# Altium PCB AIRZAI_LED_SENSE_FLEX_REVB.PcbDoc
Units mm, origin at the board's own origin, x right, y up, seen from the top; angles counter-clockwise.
Board outline 68.92 x 111.6 mm, 2 copper layers (Top Layer, Bottom Layer); 53 components, 36 nets, 162 pads, 42 vias.
Unrouted connection lines stored in the file: 83.
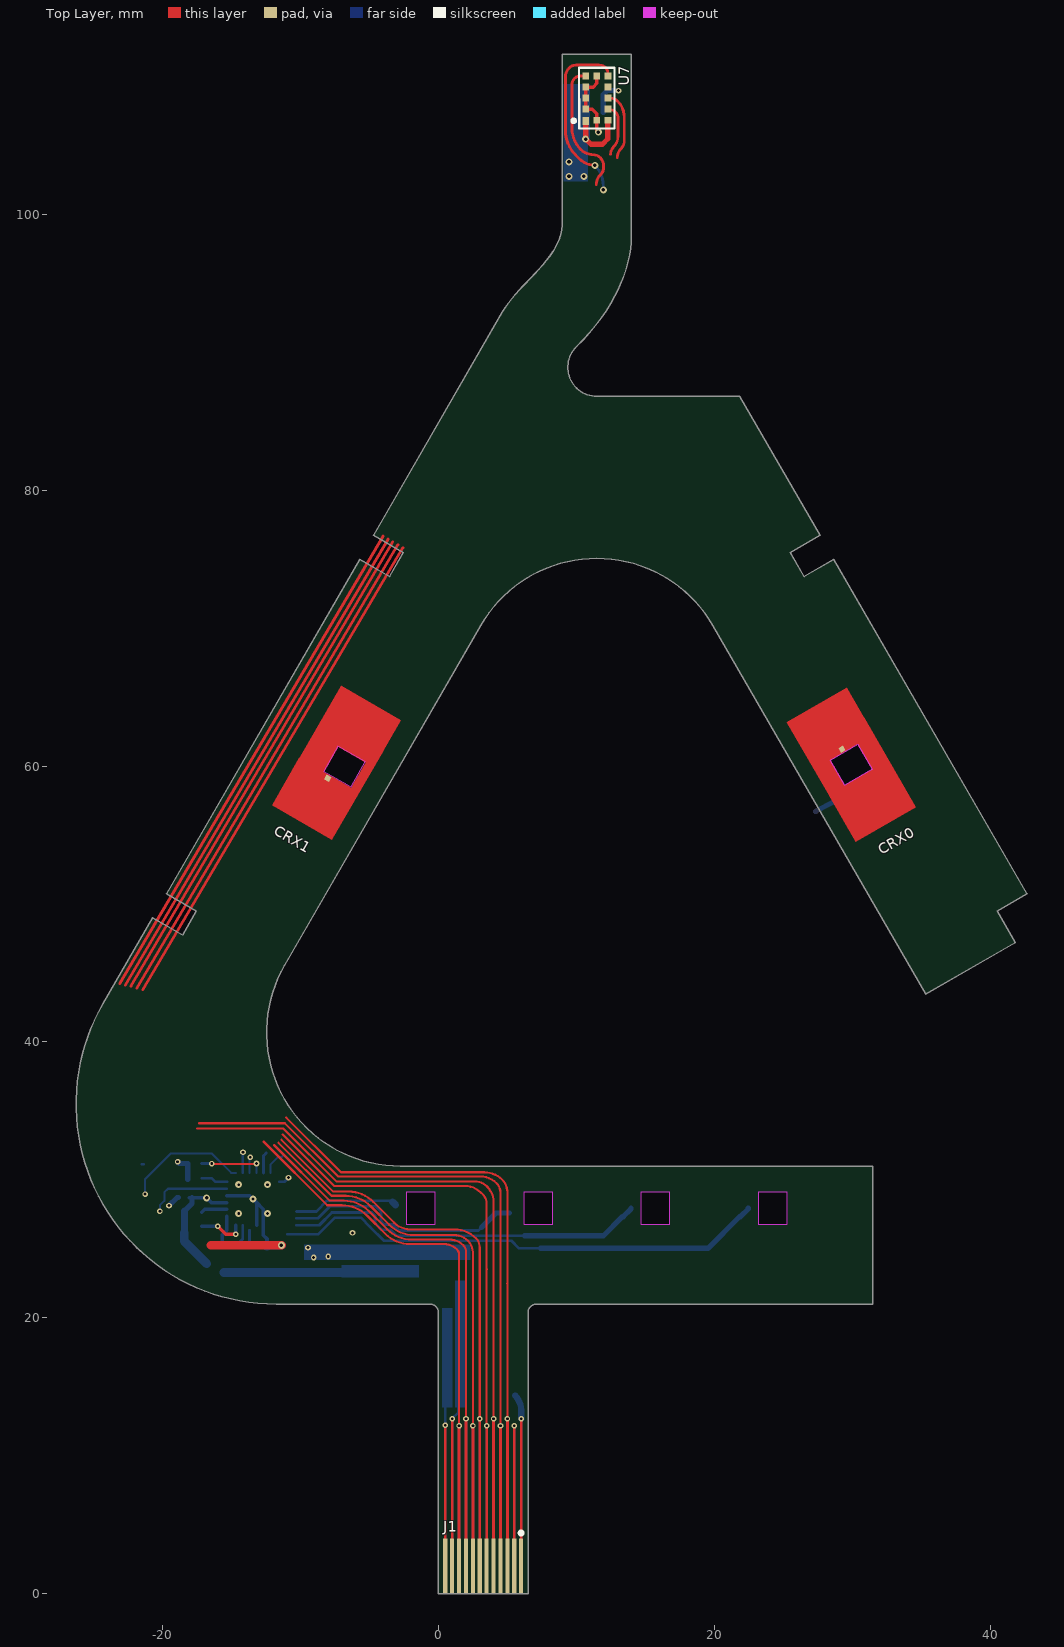
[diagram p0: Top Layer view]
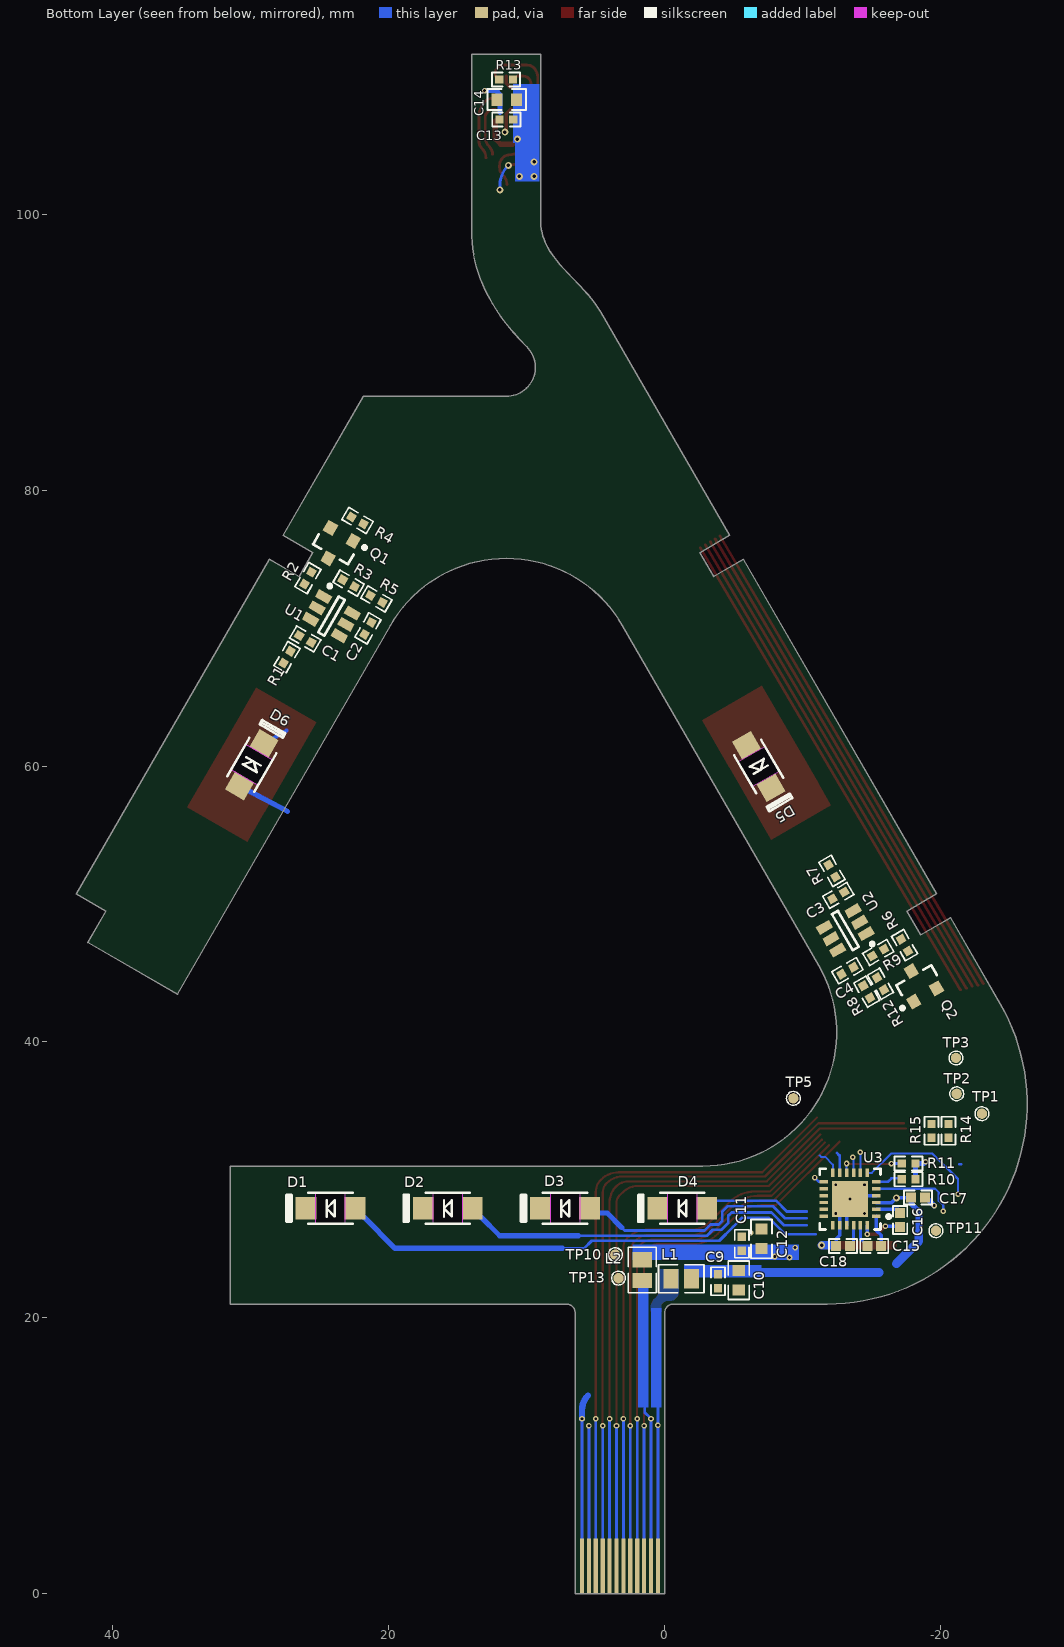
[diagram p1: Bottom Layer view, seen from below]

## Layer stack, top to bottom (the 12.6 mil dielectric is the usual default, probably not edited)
Top Solder: solder mask 0.0102, Solder Resist, Dk 3.5
Top Layer: signal copper 0.0356
Dielectric 1: dielectric 0.32, FR-4, Dk 4.8
Bottom Layer: signal copper 0.0356
Bottom Solder: solder mask 0.0102, Solder Resist, Dk 3.5

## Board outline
-11.76,21 cw(c-11.76,35.5) -24.317,42.751 -20.705,49.007 -18.54,47.757 -17.54,49.489 -19.705,50.739 -5.704,74.987 -3.539,73.736 -2.539,75.468 -4.704,76.719 4.638,92.9 cw(c11.813,88.612) 5.59,94.192 cw(c21.327,80.391) 6.151,94.807 6.73,95.412 ccw(c-15.943,117.23) 7.299,96.019 ccw(c-2.377,104.855) 7.828,96.636 ccw(c1.874,101.436) 8.29,97.273 ccw(c4.018,100.047) 8.655,97.94 ccw(c5.183,99.515) 8.895,98.645 ccw(c5.64,99.401) 8.982,99.4 8.982,100.4 8.982,111.6 13.982,111.6 13.982,100.4 13.982,98.4 cw(c6.078,98.429) 13.773,96.625 cw(c4.661,98.734) 13.526,95.753 cw(c3.528,99.114) 13.197,94.898 cw(c2.331,99.634) 12.794,94.065 cw(c0.618,100.569) 11.807,92.484 cw(c-1.263,101.927) 10.012,90.4 ccw(c11.481,88.9) 11.481,86.8 21.846,86.799 27.666,76.718 25.501,75.468 26.501,73.736 28.666,74.986 42.665,50.737 40.5,49.487 41.816,47.209 35.316,43.467 19.881,70.202 ccw(c11.481,65.352) 3.08,70.202 -11.153,45.55 ccw(c-2.753,40.7) -2.753,31 31.48,30.999 31.48,21 7.103,21 ccw(c7.106,20.394) 6.5,20.39 6.5,0 0,0 0,20.381 ccw(c-0.606,20.394) -0.594,21
cut-out: 23.18,26.8 25.28,26.8 25.28,29.1 23.18,29.1
cut-out: 14.68,26.8 16.78,26.8 16.78,29.1 14.68,29.1
cut-out: 6.18,26.8 8.28,26.8 8.28,29.1 6.18,29.1
cut-out: -2.32,26.8 -0.22,26.8 -0.22,29.1 -2.32,29.1
cut-out: 29.454,58.612 28.41,60.425 30.403,61.572 31.447,59.759
cut-out: -8.322,59.637 -6.329,58.49 -5.285,60.303 -7.278,61.45

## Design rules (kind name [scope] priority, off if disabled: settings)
Clearance Clearance_Board_Cutout_Electrodes [(InComponent('CRX0') OR InComponent('CRX1')) vs OnLayer('Multi-Layer')] p1: gap=0 ignorepadtopadclearanceinfootprint=FALSE
Clearance Clearance_Board_Cutout_Diodes [(InComponent('D1') OR InComponent('D2') OR InComponent('D3') OR InComponent('D4') OR InComponent('D5') OR InComponent('D6')) vs OnLayer('Multi-Layer')] p2: gap=0 ignorepadtopadclearanceinfootprint=FALSE
Clearance Clearance_Keepout [(OnLayer('Keep-Out Layer')) vs (InComponent('D1') OR InComponent('D2') OR InComponent('D3') OR InComponent('D4') OR InComponent('D5') OR InComponent('D6') OR InComponent('CRX0') OR InComponent('CRX1') OR InComponent('J1'))] p3: gap=0 ignorepadtopadclearanceinfootprint=FALSE
Clearance Clearance_GND_POLY_ELECTRODE [(InComponent('CRX0') OR InComponent('CRX1') OR InComponent('CRX2') OR InNet('NetCRX0_1') OR InNet('NetCRX1_1') OR InNet('NetCRX2_1') OR InNet('NetR4_2') OR InNet('NetR2_1') OR InNet('NetR1_1')) vs (InNet('GND') AND InPolygon)] p4: gap=0.762 ignorepadtopadclearanceinfootprint=FALSE
Clearance Clearance_POLYGON_KEEPOUT [(OnLayer('Keep-Out Layer')) vs (InNet('GND') AND InPolygon)] p5: gap=0.254 ignorepadtopadclearanceinfootprint=FALSE
Clearance Clearance_GND_POLY_REST [All vs (InNet('GND') AND InPolygon)] p6: gap=0.254 ignorepadtopadclearanceinfootprint=FALSE
Clearance [All] p7: gap=0.152 ignorepadtopadclearanceinfootprint=FALSE
MinimumSolderMaskSliver [All] p1: minsoldermaskwidth=0.025
PolygonConnect [All] p1: connectstyle=Direct reliefconductorwidth=0.254 reliefentries=4 polygonreliefangle="90 Angle" airgapwidth=0.254
RoomDefinition AIRZAI_LED_SENSE_FLEX_REVB [InComponentClass('AIRZAI_LED_SENSE_FLEX_REVB')] p1: confinementstyle=ConfineIn formatcopy=TRUE lockcomponents=FALSE outline -98.86,-68.935 273.504,-68.935 273.504,174.905 -98.86,174.905
RoutingVias [All] p1: holewidth=0.711 width=1.27 viastyle="Through Hole" minholewidth=0.203 minwidth=0.406 maxholewidth=0.711 maxwidth=1.27
SilkToSilkClearance [All] p1: silktosilkclearance=0.025
SilkToSolderMaskClearance [IsPad] p1: minsilkscreentomaskgap=0.051 clearancetoexposedcopper=TRUE
SolderMaskExpansion [All] p1: expansion=0.102
UnRoutedNet [All] p1: checkbadconnections=TRUE
Width [All] p1: maxlimit=2.54 minlimit=0.152 preferedwidth=0.254
26 further rules are at their usual default settings.

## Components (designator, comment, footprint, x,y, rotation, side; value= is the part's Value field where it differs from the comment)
C1 "22nF" 0402CAP 26.059,69.212 r210 bottom
C2 "0.1µF" 0402CAP 21.514,69.977 r120 bottom
C3 "22nF" 0402CAP -12.577,50.624 r330 bottom
C4 "0.1µF" 0402CAP -13.237,45.163 r150 bottom
C9 "0.1µF" 0402CAP -3.861,22.661 r270 bottom
C10 "10µF" 0603 -5.359,22.733 r270 bottom
C11 "0.1µF" 0402CAP -5.588,25.38 r90 bottom
C12 "10µF" 0603 -7.01,25.73 r90 bottom
C13 "0.1µF" 0402CAP 11.481,106.864 r0 bottom
C14 "4.7µF" 0603 11.455,108.306 r180 bottom
C15 "CAP 1uF 16V 0402(1005)" CAPC0402(1005)60_M -15.181,25.222 r0 bottom value=1uF
C16 "CAP 1uF 16V 0402(1005)" CAPC0402(1005)60_M -17.057,27.103 r270 bottom value=1uF
C17 "CAP 1uF 16V 0402(1005)" CAPC0402(1005)60_M -18.357,28.733 r0 bottom value=1uF
C18 "CAP 1uF 16V 0402(1005)" CAPC0402(1005)60_M -12.921,25.222 r0 bottom value=1uF
CRX0 "CONTACT POINT 1" "CONTACT_POINT_1CM _SQ - duplicate" 29.928,60.092 r300 top
CRX1 "CONTACT POINT 1" "CONTACT_POINT_1CM _SQ" -7.375,60.254 r60 top
D1 "WHITE" LED1206_LTW-C230DS 24.23,27.95 r0 bottom locked
D2 "WHITE" LED1206_LTW-C230DS 15.73,27.95 r0 bottom locked
D3 "WHITE" LED1206_LTW-C230DS 7.23,27.95 r0 bottom locked
D4 "WHITE" LED1206_LTW-C230DS -1.271,27.951 r0 bottom
D5 "WHITE" LED1206_LTW-C230DS -6.804,59.97 r240 bottom
D6 "WHITE" LED1206_LTW-C230DS 29.928,60.092 r120 bottom
J1 "FFC Pads" FFC_PADS 3.25,2 r0 top locked
L1 "CB2012T100KR" 0805 -1.194,22.835 r180 bottom value=10uH
L2 "CB2012T100KR" 0805 1.626,23.47 r90 bottom value=10uH
Q1 "NTR4003NT1G" SOT-23-3-NTR4003NT1G 23.904,75.921 r300 bottom
Q2 "NTR4003NT1G" SOT-23-3-NTR4003NT1G -18.368,44.274 r60 bottom
R1 "10k 0402(1005)" 0402 27.38,67.892 r300 bottom value=10k
R2 "100R 0402(1005)" 0402 25.861,73.619 r300 bottom value=100
R3 "Jumper 0402(1005)" 0402 22.911,73.254 r30 bottom value=0R
R4 "DNP 0402(1005)" 0402 22.276,77.8 r30 bottom value=DNP
R5 "DNP 0402(1005)" 0402 20.904,72.111 r210 bottom value=DNP
R6 "100R 0402(1005)" 0402 -17.378,47.017 r60 bottom value=100
R7 "10k 0402(1005)" 0402 -12.119,52.402 r60 bottom value=10k
R8 "Jumper 0402(1005)" 0402 -14.637,43.641 r240 bottom value=0R
R9 "DNP 0402(1005)" 0402 -15.469,46.484 r330 bottom value=DNP
R10 "Jumper 0402(1005)" 0402 -17.668,30.048 r0 bottom value=0R
R11 "Jumper 0402(1005)" 0402 -17.668,31.191 r0 bottom value=0R
R12 "DNP 0402(1005)" 0402 -15.628,44.22 r240 bottom value=DNP
R13 "10k 0402(1005)" 0402 11.506,109.753 r0 bottom value=10k
R14 "Jumper 0402(1005)" 0402 -20.569,33.563 r270 bottom value=0R
R15 "DNP 0402(1005)" 0402 -19.327,33.563 r90 bottom value=DNP
TP1 "Test Point" TP_0.9MM -22.988,34.806 r90 bottom
TP2 "Test Point" TP_0.9MM -21.16,36.248 r90 bottom
TP3 "Test Point" TP_0.9MM -21.105,38.846 r90 bottom
TP5 "Test Point" TP_0.9MM -9.322,35.916 r90 bottom
TP10 "Test Point" TP_0.9MM 3.581,24.587 r90 bottom
TP11 "Test Point" TP_0.9MM -19.657,26.324 r90 bottom
TP13 "Test Point" TP_0.9MM 3.353,22.885 r90 bottom
U1 "AT42QT1010-TSHR" SOT-23-6-AT42QT1010-TSHR 24.154,70.863 r210 bottom
U2 "AT42QT1010-TSHR" SOT-23-6-AT42QT1010-TSHR -13.085,48.084 r330 bottom
U3 "LP55231SQE/NOPB" WQFN-24-LP55231SQE/NOPB -13.43,28.616 r0 bottom value="IC LED DRIVER RGLTR DIM 24WQFN"
U7 "VL53L0CXV0DH/1" VL53L0X 11.481,108.407 r270 top

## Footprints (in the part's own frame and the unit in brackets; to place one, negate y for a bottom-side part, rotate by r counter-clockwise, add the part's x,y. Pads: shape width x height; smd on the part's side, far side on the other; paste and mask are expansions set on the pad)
0402 [mm] "Chip Resistor, Body 1.1x0.5mm, IPC High Density"
  rect 0.6x0.6 smd: 1(-0.5,0) 2(0.5,0)
  silkscreen extent -1.02,-0.51 1.02,0.51, body extent -0.5,-0.25 0.5,0.25, height 0.27
0402CAP [mm] "Chip Capacitor, Body 1.1x0.5mm, IPC High Density"
  rect 0.6x0.6 smd: 1(-0.5,0) 2(0.5,0)
  silkscreen extent -1.02,-0.51 1.02,0.51, body extent -0.5,-0.3 0.5,0.3, height 0.19
0603 [mm] "Chip Resistor, Body 1.6x0.8mm, IPC High Density"
  rect 0.8x0.9 smd: 1(-0.7,0) 2(0.7,0)
  silkscreen extent -1.4,-0.76 1.4,0.76, body extent -0.8,-0.41 0.8,0.4, height 0.37
0805 [mm] "Chip Resistor, Body 2.0x1.3mm, IPC High Density"
  rect 1.1x1.4 smd: 1(-0.75,0) 2(0.75,0)
  silkscreen extent -1.65,-1.02 1.65,1.02, body extent -1.02,-0.64 0.98,0.62, height 0.47
CAPC0402(1005)60_M [mm] "Chip Capacitor, Body 1.0x0.5mm, Height 0.6mm, IPC Low Density"
  rect 0.72x0.72 smd: 1(-0.5,0) 2(0.5,0)
  silkscreen extent -1.02,-0.51 1.02,0.51, body extent -0.55,-0.3 0.55,0.3, height 0.6
"CONTACT_POINT_1CM _SQ" [mm]
  rect 0.4x0.4 smd paste-2 mask-2: 1(-1.312,-0.018)
  Top Layer region: -3.216,2.5 -1.068,0.472 1.05,0.472 1.05,-2.5 5,-2.5 5,2.5
  Top Layer region: 2.48,-2.5 1.768,-1.828 -1.05,-1.828 -1.05,2.5 -5,2.5 -5,-2.5
"CONTACT_POINT_1CM _SQ - duplicate" [mm]
  rect 0.4x0.4 smd paste-2 mask-2: 1(-1.312,-0.018)
  Top Layer region: 2.48,-2.5 1.05,-1.15 -1.05,-1.15 -1.05,2.5 -5,2.5 -5,-2.5
  Top Layer region: -2.48,2.5 -1.05,1.15 1.05,1.15 1.05,-2.5 5,-2.5 5,2.5
FFC_PADS [mm] "(0.50mm"
  rect 0.3x4 smd: 1(2.75,0) 2(2.25,0) 3(1.75,0) 4(1.25,0) 5(0.75,0) 6(0.25,0) 7(-0.25,0) 8(-0.75,0) 9(-1.25,0) 10(-1.75,0) 11(-2.25,0) 12(-2.75,0)
  rect 0.3x4 smd far side: 1(2.75,0) 2(2.25,0) 3(1.75,0) 4(1.25,0) 5(0.75,0) 6(0.25,0) 7(-0.25,0) 8(-0.75,0) 9(-1.25,0) 10(-1.75,0) 11(-2.25,0) 12(-2.75,0)
  silkscreen extent 2.63,2.29 2.87,2.54
LED1206_LTW-C230DS [mm] "Chip Capacitor, Body 3.2x1.6mm, IPC High Density"
  rect 1.5x1.6 smd paste-0.1 mask+0.07: 1(1.775,0) 2(-1.775,0)
  silkscreen extent -1.6,-1.13 3.19,1.13, body extent -1.63,-0.8 1.63,0.8, height 0.31
SOT-23-3-NTR4003NT1G [mm] "SOT23, 3-Leads, Body 2.92x1.3mm, Pitch 0.95mm"
  rect 0.9x0.8 smd: 1(-1,0.95) 2(-1,-0.95) 3(1,0)
  silkscreen extent -1.12,-1.46 0.65,2.02, body extent -0.65,-1.46 0.65,1.46, height 1.11
SOT-23-6-AT42QT1010-TSHR [mm] "SOT23, 6-Leads, Body 2.9x1.6mm, Pitch 0.95mm, Lead Span 2.8mm, IPC Medium Density"
  rect 1.1x0.65 smd: 1(-1.2,0.95) 2(-1.2,0) 3(-1.2,-0.95) 4(1.2,-0.95) 5(1.2,0) 6(1.2,0.95)
  silkscreen extent -1.32,-1.5 0.25,1.95, body extent -0.88,-1.5 0.88,1.5, height 1.45
TP_0.9MM [mm] "0.9MM DIA TESTPOINT"
  round 0.75 smd paste-5 mask+0.05: 1(0,0)
  silkscreen extent -0.5,-0.5 0.5,0.5
VL53L0X [mm]
  rect 0.58x0.5 smd: 1(1.64,-0.8)
  rect 0.5x0.5 smd: 2(0.8,-0.8) 3(0,-0.8) 4(-0.8,-0.8) 5(-1.6,-0.8) 6(-1.6,0) 7(-1.6,0.8) 8(-0.8,0.8) 9(0,0.8) 10(0.8,0.8) 11(1.6,0.8) 12(1.6,0)
  silkscreen extent -2.2,-1.79 2.2,1.3, body extent -2.2,-1.3 2.2,1.3, height 3.72
WQFN-24-LP55231SQE/NOPB [mm] "QFN, 24-Leads, Body 3.97x3.97mm, Pitch 0.50mm, Thermal Pad 2.60x2.60mm, IPC Medium Density"
  rect 0.6x0.25 smd: 1(-1.9,1.25) 2(-1.9,0.75) 3(-1.9,0.25) 4(-1.9,-0.25) 5(-1.9,-0.75) 6(-1.9,-1.25) 13(1.9,-1.25) 14(1.9,-0.75) 15(1.9,-0.25) 16(1.9,0.25) 17(1.9,0.75) 18(1.9,1.25)
  rect 0.25x0.6 smd: 7(-1.25,-1.9) 8(-0.75,-1.9) 9(-0.25,-1.9) 10(0.25,-1.9) 11(0.75,-1.9) 12(1.25,-1.9) 19(1.25,1.9) 20(0.75,1.9) 21(0.25,1.9) 22(-0.25,1.9) 23(-0.75,1.9) 24(-1.25,1.9)
  rect 2.6x2.6 smd: 25(0,0)
  silkscreen extent -2.92,-2.2 2.2,2.2, body extent -2.01,-2.01 2.01,2.01, height 0.8

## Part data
C1 C3: library part C0402-100n, "Capacitor, X7R, ±10%", Case/Package=0402, Case Code (Metric)=1005, Dielectric=X7R, Manufacturer=TDK, Manufacturer Part Number=CGA2B2X7R1E223K050BA, Max Operating Temperature=125°C, Min Operating Temperature=-55°C, Package Quantity=1, Ratings=AEC-Q200, Supplier Part Number 1=445-5609-1-ND, Tolerance=10%, Voltage Rating=25V
C2 C4 C9 C11 C13: library part C0402-100n, "Capacitor, X7R, ±10%", Case-EIA=0402, Case-Metric=1005, Manufacturer=TDK, Manufacturer Part Number=C1005X7R1C104K, Rated Voltage="16 V", Supplier Part Number 1=445-4952-2-ND, Tolerance=±20%
C10 C12: library part C0402-100n, "Capacitor, X7R, ±10%", Case-EIA=0603, Case-Metric=1608, Manufacturer=MURATA, Manufacturer Part Number=GRM188R60J106ME47D, Rated Voltage="6.3 V", Supplier Part Number 1=490-3896-6-ND, Tolerance=±20%
C14: library part "C0603-1µ0 X7R", "Capacitor, X7R, ±10%", Case-EIA=0402, Case-Metric=1005, Manufacturer=TDK, Manufacturer Part Number=C1005X5R0J475M, Rated Voltage="6.3 V", Supplier Part Number 1=445-7395-2-ND, Tolerance=±20%
C15 C16 C17 C18: library part CAP, "CAP 1uF 16V ±10% 0402 (1005 Metric) Thickness 0.6mm SMD", Case-EIA=0402, Case-Metric=1005, Manufacturer="Taiyo Yuden", Manufacturer Part Number=JMK105C6105KV-F, Rated Voltage="6.3 V", Supplier Part Number 1=587-3381-1-ND, Tolerance=±10%
CRX0 CRX1: library part WIRE_POINT
D1 D2 D3 D4 D5 D6: library part LED_LTW-C230DS, Case-EIA=1206, Case-Metric=3216, Manufacturer=LITEON, Manufacturer Part Number=LTW-C230DS, Supplier Part Number 1=160-2221-1-ND
J1: library part FFC_PADS, "0.5 mm Pitch FFC Pads"
L1 L2: "Inductor, 10 µH, 0.5A, 0.65 ohm, SMD", Case/Package=0805, Case Code (Metric)=2012, Current Rating=520mA, DC Resistance (DCR)=500mR, Inductance=10uH, Inductance Tolerance=10%, Manufacturer="Taiyo Yuden", Max DC Current=200mA, Max Operating Temperature=105°C, Min Operating Temperature=-40°C, Package Quantity=3000, Self Resonant Frequency=32MHz, Supplier Part Number 1=587-2452-1-ND, Test Frequency=2.52MHz, Value1="0.65 ohm", Value2=0.5A, ValueDisplayed=10µH
Q1 Q2: "N-Channel 30V 500mA (Ta) 690mW (Ta) Surface Mount SOT-23-3 (TO-236)", Case/Package=SOT-23-3, Continuous Drain Current (ID)=500mA, Drain to Source Breakdown Voltage=30V, Drain to Source Resistance=1R, Gate to Source Voltage (Vgs)=20V, Input Capacitance=21pF, Manufacturer="ON Semiconductor", Max Operating Temperature=150°C, Max Power Dissipation=690mW, Min Operating Temperature=-55°C, Package Quantity=1, Supplier Part Number 1=NTR4003NT1GOSCT-ND, Threshold Voltage=1.4V
R1 R7 R13: library part RES, "10k 0.063W 1% 0402 (1005 Metric)  SMD", Case-EIA=0402, Case-Metric=1005, Manufacturer=Yageo, Manufacturer Part Number=RC0402FR-0710KL, Power=0.063W, Supplier Part Number 1=311-10.0KLRCT-ND, Tolerance=None
R2 R6: library part RES, "100 0.063W 1% 0402 (1005 Metric)  SMD", Case-EIA=0402, Case-Metric=1005, Manufacturer=Yageo, Manufacturer Part Number=RC0402FR-07100RL, Power=None, Supplier Part Number 1=311-100LRCT-ND
R3 R8 R10 R11 R14: library part RES, "Jumper 0402 (1005 Metric)", Case-EIA=0402, Case-Metric=1005, Manufacturer=Panasonic, Manufacturer Part Number=ERJ-2GE0R00X, Power=None, Supplier Part Number 1=P0.0JCT-ND
R4 R5 R9 R12 R15: library part RES, "DNP", Case-EIA=0402, Case-Metric=1005, Power="0.0625 W", Tolerance=None
U1 U2: "One-channel Touch Sensor IC with Reset Timer, -40° to +85° C, 6-pin SOT23", Supplier Part Number 1=AT42QT1010-TSHRCT-ND
U3: "Imported", Case-EIA=24-WQFN, Manufacturer=TI, Supplier Part Number 1=296-39059-1-ND, Tolerance=None
U7: library part VL53L0X, Case-EIA=LGA12, Manufacturer=ST, Supplier Part Number 1=497-16538-1-ND, Tolerance=None

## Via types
v1: diameter 0.406, hole 0.203, Top Layer to Bottom Layer, tented both sides, 28 vias
v2: diameter 0.508, hole 0.254, Top Layer to Bottom Layer, tented both sides, 9 vias
v3: diameter 0.508, hole 0.203, Top Layer to Bottom Layer, 5 vias

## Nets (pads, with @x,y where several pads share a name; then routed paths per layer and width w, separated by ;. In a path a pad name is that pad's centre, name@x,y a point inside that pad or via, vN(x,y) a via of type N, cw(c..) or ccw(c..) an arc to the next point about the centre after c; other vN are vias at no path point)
3V3: C2.1 C4.1 C11.1 C12.1 C13.1 C14.2 D5.2 D6.2 L2.2 R3.2 R8.2 R13.1 R14.1 TP10.1 U1.5 U2.5 U7.1 U7.11 | length 4.5
  Top Layer w0.381: U7.1 v2(10.681,105.444) 11.059,105.065 11.884,105.065 12.281,105.462 U7.11@12.281,106.727
  other v1: -9.042,24.384 -7.976,24.454 -9.449,25.095
  other v2: 9.468,102.743 10.543,102.743 9.468,103.784
+5V: C9.1 C10.1 C17.2 L1.2 TP11.1 U3.3 | length 17.4
  Bottom Layer w0.254: C17.2@-18.067,28.696 -17.857,28.696 -16.783,28.696 -16.453,28.366 U3.3
  Bottom Layer w0.381: -18.435,25.624 -18.41,25.599 ; -18.41,27.751 -17.857,28.303 -17.857,28.696 C17.2
  Bottom Layer w0.508: -18.41,26.173 -18.41,27.751
  Bottom Layer w0.635: -18.41,26.173 -18.41,25.599 -18.41,25.559 -16.787,23.936 ; -15.545,23.292 -6.782,23.292
  other v2: -16.79,28.703
CAP1_TOUCH_OUT: J1.6 Q1.1 R4.1 TP5.1 U1.1 | length 53.5
  Top Layer w0.152: -11.278,33.299 -7.544,29.566 1.93,29.566 cw(c1.93,27.971) 3.058,29.099 3.277,28.88 cw(c2.737,28.34) 3.5,28.34 3.5,23.528 ; v1(3.5,12.192) 3.5,23.528 ; 3.505,23.533 3.5,23.528
  Top Layer w0.203: J1.6@3.5,2 v1(3.5,12.192)
  Bottom Layer w0.203: J1.6@3.5,2 v1(3.5,12.192)
CAP2_TOUCH_OUT: J1.8 Q2.1 R9.1 TP3.1 U2.1 | length 50.3
  Top Layer w0.152: -11.595,32.703 -7.746,28.854 -6.716,28.854 cw(c-6.716,26.314) -4.92,28.11 -3.563,26.754 ccw(c-1.767,28.55) -1.767,26.01 1.117,26.01 cw(c1.117,24.535) 2.159,25.578 cw(c1.336,24.755) 2.5,24.755 2.5,23.607 ; v1(2.5,12.192) 2.5,23.607 ; 2.515,23.622 2.5,23.607
  Top Layer w0.203: J1.8@2.5,2 v1(2.5,12.192)
  Bottom Layer w0.203: J1.8@2.5,2 v1(2.5,12.192)
EN: J1.4 R14.2 R15.1 U3.5 | length 67.5
  Top Layer w0.152: -17.352,34.113 -11.128,34.113 -7.267,30.251 3.051,30.251 cw(c3.051,28.604) 4.216,29.769 cw(c3.542,29.094) 4.496,29.094 4.496,22.111 4.5,22.107 v1(4.5,12.192)
  Top Layer w0.203: J1.4@4.5,2 v1(4.5,12.192)
  Bottom Layer w0.152: v1(-20.185,27.728) -20.185,28.165 -19.855,28.494 -19.855,29.103 -19.592,29.366 U3.5
  Bottom Layer w0.203: J1.4@4.5,2 v1(4.5,12.192)
GND: C2.2 C4.2 C9.2 C10.2 C11.2 C12.2 C13.2 C14.1 C17.1 C18.2 D1.1 D2.1 D3.1 D4.1 J1.1 J1.2 Q1.2 Q2.2 R4.2 R5.2 R9.2 R10.1 R11.1 R12.2 R15.2 U1.2 U2.2 U3.4 U3.20 U3.21 U3.25 U7.2 U7.3 U7.4 U7.6 U7.12 | length 71.9
  Top Layer w0.203: J1.2@5.5,2 v1(5.5,12.192) ; J1.1@6,2 v1(6,12.693)
  Top Layer w0.254: U7.6 11.481,109.474 11.214,109.207 U7.4 U7.3 U7.2 11.163,107.607 11.481,107.289 U7.12 11.481,106.058 v2(11.595,105.943)
  Top Layer w0.635: -16.502,25.269 v2(-11.371,25.269)
  Bottom Layer w0.203: J1.2@5.5,2 v1(5.5,12.192) ; J1.1@6,2 v1(6,12.693)
  Bottom Layer w0.254: U3.4 -13.68,28.866 v3(-13.43,28.616) U3.25@-13.18,28.366 ; U3.21 U3.25@-13.18,28.366 ; C18.2 -12.421,25.734 -12.68,25.993 U3.20 -12.68,27.866 U3.25@-13.18,28.366
  Bottom Layer w0.381: v1(-19.525,28.139) -18.93,28.733 C17.1 ; v1(-18.897,31.314) -18.774,31.191 R11.1 R10.1 ; 11.943,107.378 11.943,108.652 12.244,108.953 v1(13.056,108.953) ; 27.347,56.713 30.816,58.555
  Bottom Layer w0.457: 5.563,14.376 cw(c4.507,13.32) 6,13.32 v1(6,12.693)
  Bottom Layer w0.635: C18.2 -12.374,25.269 v2(-11.371,25.269)
  other v1: -6.223,26.162
  other v3: -14.47,27.576 -12.39,27.576 -14.47,29.656 -12.39,29.656
INT: J1.5 U3.7 | length 70.1
  Top Layer w0.152: -17.475,33.731 -11.231,33.731 -7.396,29.896 2.639,29.896 cw(c2.639,28.635) 3.531,29.527 cw(c2.397,28.393) 4,28.393 v1(4,12.693)
  Top Layer w0.203: J1.5@4,2 v1(4,12.693)
  Bottom Layer w0.152: v1(-21.252,28.977) -21.25,28.979 -21.25,30.07 -19.396,31.923 -16.417,31.923 -15.01,30.516 U3.7
  Bottom Layer w0.203: J1.5@4,2 v1(4,12.693)
NetC1_1: C1.1 R1.1 U1.3
NetC1_2: C1.2 U1.4
NetC3_1: C3.1 R7.1 U2.3
NetC3_2: C3.2 U2.4
NetC15_1: C15.1 U3.1 | length 2.3
  Bottom Layer w0.254: C15.1 -15.681,25.988 -15.33,26.339 U3.1
NetC15_2: C15.2 U3.23 | length 1.7
  Bottom Layer w0.203: C15.2 -14.18,25.723 U3.23
NetC16_1: C16.1 U3.2 | length 1.9
  Bottom Layer w0.254: C16.1@-17.152,27.652 -16.938,27.866 U3.2
NetC16_2: C16.2 U3.24 | length 3.4
  Top Layer w0.254: v1(-15.991,26.652) -15.399,26.06 v1(-14.68,26.06) v1@-14.68,25.984
  Bottom Layer w0.254: C16.2@-17.152,26.652 v1(-15.991,26.652) ; v1(-14.68,26.06) U3.24
NetC18_1: C18.1 U3.22 | length 1.2
  Bottom Layer w0.203: -13.68,26.352 -13.68,25.405 C18.1@-13.497,25.222
NetCRX0_1: CRX0.1 R1.2
NetCRX1_1: CRX1.1 R7.2
NetD1_2: D1.2 U3.19 | length 36
  Bottom Layer w0.203: -10.938,26.072 -8.701,26.072 -7.505,27.267 -5.617,27.267 -4.953,26.603 -4.953,26.599 -3.948,25.594 5.293,25.594 5.842,25.044 7.417,25.044
  Bottom Layer w0.381: 7.417,25.044 19.549,25.044 21.845,27.341 21.895,27.341 22.455,27.9 D1.2
NetD2_2: D2.2 U3.18 | length 26.5
  Bottom Layer w0.203: -10.288,26.722 -8.635,26.722 -7.722,27.635 -4.826,27.635 -4.597,27.407 -4.597,26.873 -4.115,26.391 -3.48,26.391 -3.048,25.959 6.248,25.959
  Bottom Layer w0.381: 6.248,25.959 11.963,25.959 13.345,27.341 13.395,27.341 13.955,27.9 D2.2
NetD3_2: D3.2 U3.17 | length 17.5
  Bottom Layer w0.203: -10.288,27.222 -8.719,27.222 -7.849,28.092 -4.547,28.092 -4.166,27.711 -4.166,27.026 -3.912,26.772 -3.307,26.772 -2.876,26.34 2.907,26.34 3.124,26.557
  Bottom Layer w0.381: 3.124,26.557 4.17,27.603 D3.2@5.157,27.603
NetD4_2: D4.2 U3.16 | length 7.7
  Bottom Layer w0.203: -10.288,27.722 -8.839,27.722 -8.062,28.499 D4.2@-3.409,28.499
  Bottom Layer w0.254: D4.2@-3.409,28.499 D4.2@-3.307,28.397
  Bottom Layer w0.508: D4.2@-3.307,28.397 D4.2@-3.09,28.18
NetD5_1: D5.1 R6.2
NetD6_1: D6.1 R2.2
NetJ1_11: J1.11 L2.1 TP13.1 | length 23.4
  Top Layer w0.203: J1.11@1,2 v1(1,12.7)
  Bottom Layer w0.203: J1.11@1,2 v1(1,12.7) 1,12.709 1.448,13.157 1.448,14.503 1.422,14.478
NetJ1_12: J1.12 L1.1 | length 22.5
  Top Layer w0.203: J1.12@0.5,2 v1(0.5,12.217)
  Bottom Layer w0.203: J1.12@0.5,2 v1(0.5,12.217) 0.5,14.275
NetQ1_3: Q1.3 R2.1
NetQ2_3: Q2.3 R6.1
NetR3_1: R3.1 R5.1 U1.6
NetR8_1: R8.1 R12.1 U2.6
NetR10_2: R10.2 U3.6 | length 1.9
  Bottom Layer w0.203: R10.2@-17.145,30.12 -16.419,30.12 -16.165,29.866 U3.6
NetR11_2: R11.2 U3.10 | length 4.7
  Top Layer w0.152: v1(-16.423,31.184) -16.404,31.165 v1@-13.205,31.165
  Top Layer w0.203: v1@-13.205,31.165 v1(-13.18,31.191)
  Bottom Layer w0.152: U3.10 v1(-13.18,31.191)
  Bottom Layer w0.203: R11.2 -16.429,31.191 v1(-16.423,31.184) ; v1(-13.18,31.191) v1@-13.18,31.242
SCL: J1.10 TP1.1 U3.9 U7.10 | length 55.1
  Top Layer w0.152: -12.675,32.791 -8.052,28.169 -6.97,28.169 cw(c-6.97,25.629) -5.174,27.425 -3.843,26.093 ccw(c-2.047,27.889) -2.047,25.349 0.426,25.349 cw(c0.426,24.048) 1.346,24.968 cw(c0.975,24.597) 1.5,24.597 1.5,23.245 v1(1.5,12.192)
  Top Layer w0.203: J1.10@1.5,2 v1(1.5,12.192) ; U7.10 12.349,107.607 cw(c12.349,106.913) 12.84,107.404 cw(c12.41,106.975) 13.017,106.975 13.017,105.625 cw(c11.977,105.625) 12.713,104.889 ccw(c13.264,104.337) 12.484,104.337
  Bottom Layer w0.152: U3.9 v1@-13.68,31.54
  Bottom Layer w0.203: J1.10@1.5,2 v1(1.5,12.192)
  other v1: -13.629,31.642
SDA: J1.9 TP2.1 U3.8 U7.9 | length 57
  Top Layer w0.152: -11.913,32.537 -7.874,28.499 -6.843,28.499 cw(c-6.843,25.959) -5.047,27.755 -3.716,26.423 ccw(c-1.92,28.219) -1.92,25.679 0.813,25.679 cw(c0.813,24.269) 1.81,25.266 1.829,25.248 cw(c1.415,24.834) 2,24.834 2,22.675 v1(2,12.693)
  Top Layer w0.203: J1.9@2,2 v1(2,12.693) ; U7.9 12.471,108.407 cw(c12.471,107.67) 12.992,108.191 cw(c11.827,107.026) 13.475,107.026 13.475,105.314 cw(c12.694,105.314) 13.246,104.762 ccw(c13.921,104.088) 12.967,104.088
  Bottom Layer w0.152: U3.8 -14.18,31.884 v1@-14.162,31.902
  Bottom Layer w0.203: J1.9@2,2 v1(2,12.693) v1@2.007,12.7
  other v1: -14.162,32.004
TOFINT: J1.7 U7.7 | length 64.9
  Top Layer w0.152: -11.379,32.918 -7.62,29.159 -6.513,29.159 cw(c-6.513,26.619) -4.717,28.415 -3.2,26.899 ccw(c-2.035,28.064) -2.035,26.416 1.149,26.416 cw(c1.149,24.161) 2.743,25.756 cw(c2.123,25.136) 3,25.136 3,23.721 ; 2.997,23.724 3,23.721 ; v1(3,12.693) 3,23.721
  Top Layer w0.203: J1.7@3,2 v1(3,12.693) ; v2(11.341,103.543) cw(c11.341,105.102) 10.239,103.999 9.951,104.287 cw(c11.747,106.083) 9.207,106.083 9.207,109.93 cw(c10.161,109.93) 9.487,110.604 cw(c9.977,110.114) 9.977,110.807 11.645,110.807 cw(c11.645,110.124) 12.128,110.607 cw(c11.76,110.239) 12.281,110.239 U7.7
  Bottom Layer w0.203: J1.7@3,2 v1(3,12.693) ; v2(11.341,103.543) cw(c9.869,102.071) 11.951,102.071 v2(11.951,101.765)
XSHUNT: J1.3 R13.2 U7.5 | length 66.2
  Top Layer w0.152: -11.024,34.519 -7.061,30.556 3.335,30.556 cw(c3.335,28.735) 4.623,30.023 cw(c3.712,29.112) 5,29.112 5,22.483 ; 4.978,22.504 5,22.483 ; v1(5,12.693) 5,22.483
  Top Layer w0.203: J1.3@5,2 v1(5,12.693) ; U7.5 10.266,110.007 ccw(c10.266,109.444) 9.868,109.842 ccw(c10.323,109.387) 9.679,109.387 9.679,106.245 ccw(c11.884,106.245) 10.325,104.686 ccw(c11.245,105.606) 11.245,104.305 cw(c11.245,103.626) 11.725,104.106 cw(c11.119,103.5) 11.976,103.5 11.976,103.391 cw(c11.221,103.391) 11.755,102.857 11.725,102.827 ccw(c12.406,102.146) 11.443,102.146
  Bottom Layer w0.203: J1.3@5,2 v1(5,12.693)
pads on no net: U3.11 U3.12 U3.13 U3.14 U3.15 U7.8
copper on no net: | length 193.2
  Top Layer w0.203: -23.099,44.244 -4.003,76.672 ; -22.693,44.117 -3.645,76.462 ; -22.283,44.041 -3.308,76.263 ; -21.864,43.889 -2.93,76.04 ; -21.432,43.787 -2.565,75.825
  Bottom Layer w0.152: -21.511,31.136 -21.333,31.136 ; -12.18,30.516 -12.18,31.108 -11.618,31.67 -11.338,31.67 -11.224,31.785
  Bottom Layer w0.203: -12.68,30.516 -12.68,31.785 ; -12.646,31.785 -12.473,31.958 ; -11.53,29.866 -11.168,29.866 v1(-10.863,30.171)
  Bottom Layer w0.305: 27.414,62.568 29.041,61.629

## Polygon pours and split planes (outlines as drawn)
NetJ1_12 on Bottom Layer "Bottom Layer-NetJ1_12" (solid, remove dead copper, pour order 0): 1.016,20.472 1.016,20.774 ccw(c0.149,20.774) 0.762,21.387 0.632,21.516 cw(c1.239,22.123) 0.381,22.123 0.381,23.533 -0.991,23.533 -0.998,23.525 -0.998,21.797 ccw(c-0.625,21.797) -0.889,21.533 -0.706,21.35 ccw(c-0.489,21.566) -0.489,21.26 -0.33,21.26 cw(c-0.33,20.585) 0.147,21.062 0.152,21.057 cw(c-0.093,20.811) 0.254,20.811 0.254,20.472

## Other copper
Top Layer:
  pour cut-out: 0,4.506 0,0 6.551,0 6.551,4.506
Bottom Layer:
  rectangle net 3V3: -9.728,24.201 2.337,25.34
  rectangle net +5V: -7.01,22.915 -1.397,23.82
  rectangle net NetJ1_11: 1.194,13.513 1.956,22.72
  rectangle net NetJ1_12: 0.254,13.513 1.016,20.726
  rectangle net 3V3: 9.621,105.139 10.985,109.436
  rectangle net 3V3: 9.08,102.362 10.858,109.436
  pour cut-out: -15.63,30.806 cw(c-15.662,30.774) -15.617,30.774 -15.617,26.4 -11.281,26.4 -11.281,30.816 -15.613,30.816
  pour cut-out: 0,4.506 0,0 6.525,0 6.525,4.506

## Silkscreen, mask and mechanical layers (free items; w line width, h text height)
Mechanical 1:
  drawing of 2386 lines, arcs and shapes, not listed
  text "5" at 207.18,109.863 h3.5
  text "10,4" at -77.793,108.912 h3.5
  text "R2,1" at 12.875,93.875 h3.5 r16.49
  text "R9,7" at 11.106,76.167 h3.5 r295.83
  text "44,27" at 43.403,73.683 h3.5 r300
  text "44,27" at 171.537,70.7 h3.5 r60
  text "10" at 13.706,63.609 h3.5 r30
  text "10" at -19.629,63.12 h3.5 r330
  text "79,4" at 139.397,56.596 h3.5 r90
  text "65,8" at 148.574,53.746 h3.5 r90
  text "R9,7" at -31.783,49.133 h3.5 r352.12
  text "0,4" at -67.157,37.491 h3.5
  text "10" at 52.914,35.72 h3.5 r90
  text "R14,5" at -35.824,31.665 h3.5 r19.4
  text "57,74" at 203.18,13.02 h3.5
Mechanical 2:
  lines w0.013: 16.462,86.832 16.462,104.032
Mechanical 3:
  lines w0.152: 13.172,107.396 13.172,107.879
Mechanical 4:
  lines w0.127: -24.317,42.751 ccw(c-11.76,35.5) -11.76,21 -0.594,21 cw(c-0.606,20.394) 0,20.381 0,0 6.5,0 6.5,20.39 cw(c7.106,20.394) 7.103,21 31.48,21 31.48,30.999 -2.753,31 cw(c-2.753,40.7) -11.153,45.55 3.08,70.202 cw(c11.481,65.352) 19.881,70.202 35.316,43.467 41.816,47.209 40.5,49.487 42.665,50.737 28.666,74.986 26.501,73.736 25.501,75.468 27.666,76.718 21.846,86.799 11.481,86.8 cw(c11.481,88.9) 10.012,90.4 ccw(c-1.263,101.927) 11.807,92.484 ccw(c0.618,100.569) 12.794,94.065 ccw(c2.331,99.634) 13.197,94.898 ccw(c3.528,99.114) 13.526,95.753 ccw(c4.661,98.734) 13.773,96.625 ccw(c6.078,98.429) 13.982,98.4 13.982,100.4 13.982,111.6 8.982,111.6 8.982,100.4 8.982,99.4 cw(c5.64,99.401) 8.895,98.645 cw(c5.183,99.515) 8.655,97.94 cw(c4.018,100.047) 8.29,97.273 cw(c1.874,101.436) 7.828,96.636 cw(c-2.377,104.855) 7.299,96.019 cw(c-15.943,117.23) 6.73,95.412 6.151,94.807 ccw(c21.327,80.391) 5.59,94.192 ccw(c11.813,88.612) 4.638,92.9 -4.704,76.719 -2.539,75.468 -3.539,73.736 -5.704,74.987 -19.705,50.739 -17.54,49.489 -18.54,47.757 -20.705,49.007 -24.317,42.751
Mechanical 12:
  circle w0.013: c-6.769,59.95 r2.5
  circle w0.013: c30.231,59.949 r2.5
  circle w0.013: c-6.769,59.95 r1.5
  circle w0.013: c30.231,59.949 r1.5
  circle w0.013: c24.23,27.949 r2.5
  circle w0.013: c15.73,27.95 r2.5
  circle w0.013: c7.23,27.95 r2.5
  circle w0.013: c-1.27,27.95 r2.5
  circle w0.013: c24.23,27.949 r1.5
  circle w0.013: c15.73,27.95 r1.5
  circle w0.013: c7.23,27.95 r1.5
  circle w0.013: c-1.27,27.95 r1.5
  circle w0.013: c24.23,27.949 r2.5
  circle w0.013: c15.73,27.95 r2.5
  circle w0.013: c7.23,27.95 r2.5
  circle w0.013: c-1.27,27.95 r2.5
  circle w0.013: c24.23,27.949 r1.5
  circle w0.013: c15.73,27.95 r1.5
  circle w0.013: c7.23,27.95 r1.5
  circle w0.013: c-1.27,27.95 r1.5
  lines w0.013: 81.701,-20.889 81.701,-21.389 86.701,-21.389 86.701,-20.889 ; 84.241,121.047 84.241,121.547 89.241,121.547 89.241,121.047 ; 87.701,-20.889 87.701,-21.389 92.701,-21.389 92.701,-20.889 ; 90.241,121.047 90.241,121.547 95.241,121.547 95.241,121.047 ; 96.201,-20.889 96.201,-21.389 101.201,-21.389 101.201,-20.889 ; 98.741,121.047 98.741,121.547 103.741,121.547 103.741,121.047 ; 99.202,25.297 99.702,25.297 ; 99.202,25.298 99.202,30.296 99.702,30.297 ; 99.202,57.297 99.702,57.297 ; 99.202,57.298 99.202,62.296 ; 99.202,62.297 99.702,62.297 ; 104.701,-20.889 104.701,-21.389 109.701,-21.389 109.701,-20.889 ; 107.241,121.047 107.241,121.547 112.241,121.547 112.241,121.047 ; 113.201,-20.889 113.201,-21.389 118.201,-21.389 118.201,-20.889 ; 115.741,121.047 115.741,121.547 120.741,121.547 120.741,121.047 ; 118.701,-20.889 118.701,-21.389 123.701,-21.389 123.701,-20.889 ; 121.241,121.047 121.241,121.547 126.241,121.547 126.241,121.047 ; 159.614,71.227 cw(c159.894,69.754) 159.894,71.254 ; 160.612,68.437 ccw(c159.894,69.754) 160.769,68.535 ; 161.32,70.22 cw(c159.894,69.754) 161.388,69.622 ; 164.834,38.814 cw(c165.895,37.754) 164.953,38.922 ; 164.834,36.693 ccw(c165.895,37.754) 164.954,36.586 ; 166.836,36.586 ccw(c165.895,37.754) 166.956,36.693 ; 166.836,38.922 cw(c165.895,37.754) 166.955,38.814 ; 173.334,36.693 ccw(c174.395,37.754) 173.454,36.586 ; 173.334,38.815 cw(c174.395,37.754) 173.453,38.922 ; 175.336,36.586 ccw(c174.395,37.754) 175.456,36.693 ; 175.336,38.922 cw(c174.395,37.754) 175.455,38.815 ; 179.527,61.271 cw(c179.806,59.797) 179.806,61.297 ; 180.524,58.48 ccw(c179.806,59.797) 180.681,58.578 ; 181.232,60.263 cw(c179.806,59.797) 181.3,59.665 ; 181.834,36.694 ccw(c182.895,37.754) 181.954,36.586 ; 181.834,38.815 cw(c182.895,37.754) 181.953,38.922 ; 183.836,36.586 ccw(c182.895,37.754) 183.956,36.694 ; 183.836,38.922 cw(c182.895,37.754) 183.955,38.815 ; 184.746,26.736 ccw(c185.807,27.797) 184.866,26.629 ; 184.746,28.858 cw(c185.807,27.797) 184.866,28.965 ; 186.748,26.629 ccw(c185.807,27.797) 186.868,26.736 ; 186.748,28.965 cw(c185.807,27.797) 186.868,28.858 ; 190.334,36.694 ccw(c191.395,37.754) 190.454,36.587 ; 190.334,38.815 cw(c191.395,37.754) 190.453,38.922 ; 192.336,36.587 ccw(c191.395,37.754) 192.456,36.694 ; 192.336,38.922 cw(c191.395,37.754) 192.455,38.815 ; 193.246,26.737 ccw(c194.307,27.797) 193.366,26.629 ; 193.246,28.858 cw(c194.307,27.797) 193.366,28.965 ; 195.248,26.629 ccw(c194.307,27.797) 195.368,26.737 ; 195.248,28.965 cw(c194.307,27.797) 195.368,28.858 ; 198.209,70.476 cw(c196.894,69.755) 198.292,70.298 ; 201.746,26.737 ccw(c202.807,27.797) 201.866,26.63 ; 201.746,28.858 cw(c202.807,27.797) 201.866,28.965 ; 203.748,26.63 ccw(c202.807,27.797) 203.868,26.737 ; 203.748,28.965 cw(c202.807,27.797) 203.868,28.858 ; 210.246,26.737 ccw(c211.307,27.798) 210.366,26.63 ; 210.246,28.858 cw(c211.307,27.798) 210.366,28.965 ; 212.248,28.965 cw(c211.307,27.798) 212.368,28.858 ; 212.248,26.63 ccw(c211.307,27.798) 212.368,26.737 ; 218.122,60.519 cw(c216.806,59.798) 218.204,60.342
Drill Drawing:
  text "PWB, LED SENSE FLEX" at 191.858,-92.579 h4
  text "PWB-020218-001" at 196.608,-100.854 h3.25
  text "1" at 258.208,-102.354 h2
  text "1" at 253.408,-102.454 h2
Mechanical 17:
  text "PWA, LED SENSE FLEX" at 192.941,-94.474 h4
  text "PWA-020218-001" at 197.868,-101.865 h3.25
  text "1" at 253.208,-102.154 h1.5
  text "1" at 258.008,-102.154 h1.5
  text "NOTES: /  / 1. ALL ASSEMBLY MATERIALS TO BE RoHS COMPLIANT. /  / 2. MATERIAL: /           • FLEXIBLE METAL CLAD DIELECTRIC IAW                 /             IPC-4204/11 E1E2 O0/0 CU W7 T/T /           • STIFFENER IAW IPC-4203/1-E1E8M1 /  / 3. FINISH:  IMMERSION GOLD /  / ALL EXPOSED CONDUCTIVE PATTERN AREAS NOT COVERED WITH COVERLAY MATERIAL OR OTHER PLATING  / SHALL BE IMMERSION GOLD (0.000030-0.000090 mm) OVER ELECTROLESS NICKEL (0.001-0.006 mm). /  / 4. LEGEND SHALL BE WHITE, PERMANENT, ORGANIC, NON-CONDUCTIVE UV OR EPOXY TYPE INK APPLIED  / TO THE TOP SIDE OF THE BOARD. THERE SHALL BE NO LEGEND ON ANY SOLDERABLE COMPONENT LAND. /  / 5. ALL ASSEMBLY MATERIALS TO BE RoHS COMPLIANT. /  / 6. ANY LABELS OR COMPOSITION OF, APPLIED TO THE BOARD NEED TO BE APPROVIED BY AIRZAI /  / 7. MINIMUM TRACE WIDTHS: /           EXTERNAL: 0.203 mm  INTERNAL: N/A /  / 8. MINIMUM SPACE BETWEEN FEATURES: /          EXTERNAL: 0.15 mm  INTERNAL: N/A /  / 9. Overall Board Thickness: 0.1mm" at -101.879,-176.86 h2
Mechanical 18:
  lines w0.127: -104.72,-48.914 -99.64,-48.914 ; -104.72,11.411 -99.64,11.411 ; -104.72,71.736 -99.64,71.736 ; -41.22,-109.239 -41.22,-104.159 ; -41.22,126.981 -41.22,132.061 ; 22.28,-109.239 22.28,-104.159 ; 22.28,126.981 22.28,132.061 ; 85.78,-109.239 85.78,-104.159 ; 85.78,126.981 85.78,132.061 ; 149.28,-109.239 149.28,-104.159 ; 149.28,126.981 149.28,132.061 ; 156.879,-96.595 271.179,-96.595 ; 156.879,-90.455 184.074,-90.455 ; 156.879,-84.51 184.074,-84.51 ; 156.879,-79.155 184.074,-79.155 ; 156.9,-104.159 271.2,-104.159 ; 172.774,-104.24 172.774,-73.76 ; 184.074,-104.215 184.074,-73.735 ; 184.074,-87.275 271.176,-87.275 ; 192.709,-73.735 271.179,-73.735 ; 194.979,-73.735 156.879,-73.735 ; 212.78,-109.239 212.78,-104.159 ; 212.78,126.981 212.78,132.061 ; 261.619,-104.215 261.619,-96.595 ; 271.2,-73.679 271.2,-104.159 ; 271.2,-48.914 276.28,-48.914 ; 271.2,11.411 276.28,11.411 ; 271.2,71.736 276.28,71.736 ; 121.319,-104.215 156.879,-104.215 ; 121.319,-104.215 156.879,-104.215 ; 121.319,-104.215 121.319,-73.735 156.879,-73.735 ; 156.879,-104.215 271.179,-104.215 ; 156.879,-104.215 271.179,-104.215 ; 156.879,-104.215 156.879,-73.735 ; 271.179,-104.215 271.179,-73.735 ; 271.179,-104.215 271.179,-73.735 ; 271.2,-104.159 271.2,126.981 -99.64,126.981 -99.64,-104.159 271.2,-104.159 ; -104.72,-109.239 -104.72,132.061 276.28,132.061 276.28,-109.239 -104.72,-109.239
  text "1" at -73.444,128.759 h1.78
  text "2" at -10.055,128.759 h1.78
  text "3" at 53.175,128.759 h1.78
  text "4" at 116.844,128.759 h1.78
  text "5" at 180.318,128.759 h1.78
  text "6" at 243.945,128.759 h1.78
  text "A" at -102.815,99.727 h1.78
  text "A" at 273.105,99.727 h1.78
  text "B" at -102.815,39.275 h1.78
  text "B" at 273.105,39.275 h1.78
  text "C" at -102.815,-21.05 h1.78
  text "C" at 273.105,-21.05 h1.78
  text "AIRZAI PROPRIETARY & CONFIDENTIAL" at 160.84,-70.919 h3.25
  text "DATE:" at 173.549,-75.315 h1.14
  text "ENGINEER:" at 157.449,-75.475 h1.14
  text "UNLESS OTHERWISE SPECIFIED" at 123.849,-77.015 h1.5
  text "05/13/19" at 173.736,-78.074 h1.5
  text "FD" at 162.348,-78.233 h2
  text "DIMENSIONS ARE IN MM" at 126.949,-80.215 h1.5
  text "PCB DESIGNER:" at 157.349,-80.768 h1.14
  text "DATE:" at 173.249,-80.815 h1.14
  text "D" at -102.815,-81.248 h1.78
  text "D" at 273.105,-81.248 h1.78
  text "AIRZAI" at 191.465,-82.219 h3.25
  text "TOLERANCES" at 132.049,-83.415 h1.5
  text "05/13/19" at 173.736,-83.524 h1.5
  text "DFM" at 161.678,-83.564 h2
  text "DATE:" at 173.249,-86.215 h1.14
  text "CHECK" at 157.349,-86.268 h1.14
  text "ANGULAR" at 144.349,-87.415 h1.5
  text "DECIMALS" at 123.949,-87.715 h1.5
  text "TITLE:" at 185.39,-88.894 h1.14
  text "FD" at 163.348,-89.233 h2
  text ".XX +/- .127MM" at 122.749,-91.715 h1.5
  text "+/-" at 144.049,-91.815 h1.5
  text "REL" at 157.649,-92.135 h1.14
  text "DATE:" at 173.649,-92.315 h1.14
  text "FD" at 163.098,-94.733 h2
  text ".XXX +/- .080MM" at 122.449,-95.815 h1.5
  text "REV:" at 262.189,-98.215 h1.14
  text "SCALE:" at 173.789,-98.235 h1.14
  text "DWG NO:" at 185.249,-98.435 h1.14
  text "SIZE" at 157.649,-98.515 h1.14
  text "B" at 162.824,-101.832 h3.05
  text "DO NOT SCALE DRAWING" at 123.849,-101.915 h1.8
  text "A" at 264.315,-102.319 h3.05
  text "1:1" at 175.024,-102.432 h3.05
  text "SHEET" at 247.849,-103.235 h1.14
  text "OF" at 254.549,-103.235 h1.14
  text "1" at -73.444,-107.461 h1.78
  text "2" at -10.055,-107.461 h1.78
  text "3" at 53.175,-107.461 h1.78
  text "4" at 116.844,-107.461 h1.78
  text "5" at 180.318,-107.461 h1.78
  text "6" at 243.945,-107.461 h1.78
